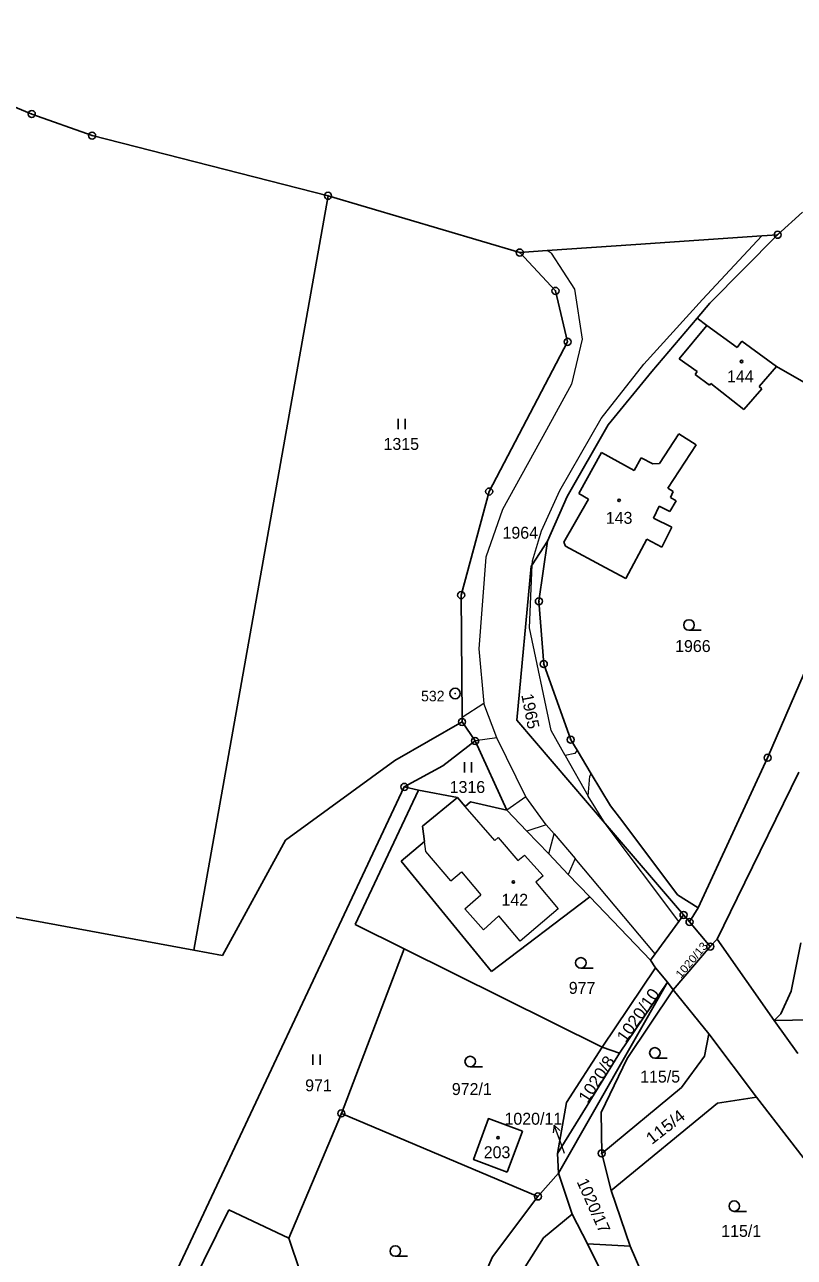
# Model space of a CAD drawing. Extents: x -601131 to -597152, y -1058536 to -1055911.
# Drawn here: x -599499.1 to -599389.4, y -1056477.3 to -1056301.8 of the extents above; entities that cross this region are included whole.
import ezdxf
from ezdxf.enums import TextEntityAlignment as Align

# ---------------------------------------------------------------- set-up
doc = ezdxf.new("R2010")
doc.units = 0
doc.header["$LTSCALE"] = 0.68
for name, color, linetype, lineweight in [('1', 7, 'Continuous', 25), ('3', 7, 'Continuous', 25), ('4', 7, 'Continuous', 13), ('5', 7, 'Continuous', 25), ('7', 7, 'Continuous', 13), ('8', 7, 'Continuous', 25)]:
    doc.layers.add(name, color=color, linetype=linetype, lineweight=lineweight)
doc.layers.add('2', color=7, linetype='Continuous')

msp = doc.modelspace()

# ---------------------------------------------------------------- linework, layer by layer
at = {"layer": '1'}
for p, q in [((-599529.09, -1056301.76), (-599498.05, -1056314.49)), ((-599498.05, -1056314.49), (-599489.45, -1056317.56)), ((-599455.85, -1056326.14), (-599474.95, -1056433.6)), ((-599388.26, -1056328.46), (-599391.8, -1056331.69)), ((-599411.98, -1056333.08), (-599424.64, -1056333.95)), ((-599394.07, -1056331.85), (-599411.98, -1056333.08)), ((-599391.8, -1056331.69), (-599401.45, -1056341.44)), ((-599394.07, -1056331.85), (-599391.8, -1056331.69)), ((-599428.53, -1056334.22), (-599424.64, -1056333.95)), ((-599428.53, -1056334.22), (-599423.44, -1056339.68)), ((-599423.44, -1056339.68), (-599421.72, -1056346.94)), ((-599401.45, -1056341.44), (-599403.27, -1056343.58)), ((-599403.27, -1056343.58), (-599409.73, -1056351.18)), ((-599403.27, -1056343.58), (-599401.88, -1056344.6)), ((-599405.8, -1056349.35), (-599401.88, -1056344.6)), ((-599401.88, -1056344.6), (-599397.54, -1056347.76)), ((-599421.72, -1056346.94), (-599432.89, -1056368.26)), ((-599397.54, -1056347.76), (-599396.88, -1056346.86)), ((-599396.88, -1056346.86), (-599391.94, -1056350.46)), ((-599403.25, -1056351.18), (-599405.8, -1056349.35)), ((-599391.94, -1056350.46), (-599394.41, -1056353.32)), ((-599391.94, -1056350.46), (-599373.7, -1056360.91)), ((-599409.73, -1056351.18), (-599415.96, -1056358.77)), ((-599403.56, -1056351.61), (-599403.25, -1056351.18)), ((-599401.51, -1056353.12), (-599403.56, -1056351.61)), ((-599401.31, -1056352.87), (-599401.51, -1056353.12)), ((-599396.61, -1056356.6), (-599401.31, -1056352.87)), ((-599394.05, -1056353.63), (-599396.61, -1056356.6)), ((-599394.41, -1056353.32), (-599394.05, -1056353.63)), ((-599415.96, -1056358.77), (-599421.77, -1056368.99)), ((-599408.63, -1056364.27), (-599405.85, -1056360.04)), ((-599405.85, -1056360.04), (-599403.42, -1056361.62)), ((-599393.22, -1056406.18), (-599373.7, -1056360.91)), ((-599420.12, -1056368.56), (-599416.89, -1056362.69)), ((-599416.89, -1056362.69), (-599412.24, -1056365.26)), ((-599403.42, -1056361.62), (-599407.44, -1056367.8)), ((-599412.24, -1056365.26), (-599411.23, -1056363.44)), ((-599411.23, -1056363.44), (-599409.58, -1056364.34)), ((-599409.58, -1056364.34), (-599408.63, -1056364.27)), ((-599432.89, -1056368.26), (-599436.88, -1056383.02)), ((-599407.44, -1056367.8), (-599406.69, -1056368.28)), ((-599406.69, -1056368.28), (-599407.08, -1056369.09)), ((-599421.77, -1056368.99), (-599424.57, -1056375.34)), ((-599422.25, -1056375.49), (-599418.74, -1056369.35)), ((-599418.74, -1056369.35), (-599420.12, -1056368.56)), ((-599406.27, -1056369.57), (-599407.15, -1056371.12)), ((-599407.08, -1056369.09), (-599406.27, -1056369.57)), ((-599408.65, -1056370.37), (-599409.49, -1056372.05)), ((-599407.15, -1056371.12), (-599408.65, -1056370.37)), ((-599409.49, -1056372.05), (-599406.86, -1056373.35)), ((-599406.86, -1056373.35), (-599408.27, -1056376.19)), ((-599424.57, -1056375.34), (-599426.76, -1056378.69)), ((-599424.57, -1056375.34), (-599425.81, -1056383.89)), ((-599422.03, -1056376.04), (-599422.25, -1056375.49)), ((-599410.45, -1056375.05), (-599413.41, -1056380.67)), ((-599408.27, -1056376.19), (-599410.45, -1056375.05)), ((-599416.35, -1056379.09), (-599422.03, -1056376.04)), ((-599426.9, -1056378.9), (-599428.95, -1056400.81)), ((-599426.76, -1056378.69), (-599426.9, -1056378.9)), ((-599413.41, -1056380.67), (-599416.35, -1056379.09)), ((-599436.88, -1056383.02), (-599436.76, -1056400.43)), ((-599425.81, -1056383.89), (-599425.11, -1056392.84)), ((-599425.11, -1056392.84), (-599421.27, -1056403.61)), ((-599436.76, -1056401.08), (-599446.33, -1056406.57)), ((-599436.76, -1056400.43), (-599436.76, -1056401.08)), ((-599436.76, -1056401.08), (-599434.89, -1056403.79)), ((-599428.95, -1056400.81), (-599416.35, -1056415.54)), ((-599420.36, -1056405.12), (-599421.27, -1056403.61)), ((-599439.48, -1056407.32), (-599434.89, -1056403.79)), ((-599434.89, -1056403.79), (-599430.37, -1056413.65)), ((-599420.36, -1056405.12), (-599418.36, -1056408.45)), ((-599446.33, -1056406.57), (-599461.89, -1056417.94)), ((-599403.1, -1056427.58), (-599393.22, -1056406.18)), ((-599444.98, -1056410.33), (-599439.48, -1056407.32)), ((-599418.36, -1056408.45), (-599415.59, -1056413.04)), ((-599388.77, -1056408.24), (-599397.57, -1056426.19)), ((-599444.98, -1056410.33), (-599484.45, -1056494.21)), ((-599444.98, -1056410.33), (-599442.97, -1056410.79)), ((-599451.98, -1056429.95), (-599442.97, -1056410.79)), ((-599442.97, -1056410.79), (-599437.4, -1056411.83)), ((-599442.37, -1056415.95), (-599437.4, -1056411.83)), ((-599437.4, -1056411.83), (-599436.29, -1056413.11)), ((-599474.95, -1056433.6), (-599583.89, -1056413.57)), ((-599435.55, -1056412.47), (-599436.29, -1056413.11)), ((-599435.55, -1056412.47), (-599430.37, -1056413.65)), ((-599430.37, -1056413.65), (-599427.52, -1056416.63)), ((-599415.59, -1056413.04), (-599413.85, -1056415.3)), ((-599416.35, -1056415.54), (-599405.2, -1056428.57)), ((-599413.85, -1056415.3), (-599406.08, -1056425.73)), ((-599442.1, -1056418.09), (-599442.37, -1056415.95)), ((-599424.4, -1056419.89), (-599427.52, -1056416.63)), ((-599461.89, -1056417.94), (-599470.88, -1056434.35)), ((-599442.1, -1056418.09), (-599445.41, -1056420.93)), ((-599445.41, -1056420.93), (-599432.54, -1056436.64)), ((-599421.62, -1056422.79), (-599424.4, -1056419.89)), ((-599421.62, -1056422.79), (-599418.55, -1056425.99)), ((-599418.55, -1056425.99), (-599432.54, -1056436.64)), ((-599418.55, -1056425.99), (-599409.9, -1056435.03)), ((-599406.08, -1056425.73), (-599403.1, -1056427.58)), ((-599397.57, -1056426.19), (-599400.42, -1056432.01)), ((-599404.35, -1056429.57), (-599403.1, -1056427.58)), ((-599444.99, -1056433.39), (-599451.98, -1056429.95)), ((-599405.88, -1056429.51), (-599409.22, -1056434.1)), ((-599405.2, -1056428.57), (-599405.88, -1056429.51)), ((-599404.35, -1056429.57), (-599405.2, -1056428.57)), ((-599401.4, -1056433.08), (-599404.35, -1056429.57)), ((-599453.95, -1056456.84), (-599444.99, -1056433.39)), ((-599444.99, -1056433.39), (-599416.78, -1056447.42)), ((-599406.68, -1056439.22), (-599401.4, -1056433.08)), ((-599400.42, -1056432.01), (-599401.4, -1056433.08)), ((-599400.42, -1056432.01), (-599392.27, -1056443.62)), ((-599388.49, -1056432.53), (-599389.89, -1056439.45)), ((-599470.88, -1056434.35), (-599474.95, -1056433.6)), ((-599409.9, -1056435.03), (-599409.22, -1056434.1)), ((-599409.9, -1056435.03), (-599409.18, -1056436.11)), ((-599409.18, -1056436.11), (-599416.78, -1056447.42)), ((-599409.18, -1056436.11), (-599407.49, -1056438.17)), ((-599422.99, -1056465.36), (-599407.49, -1056438.17)), ((-599407.49, -1056438.17), (-599414.32, -1056448.25)), ((-599407.49, -1056438.17), (-599406.68, -1056439.22)), ((-599406.68, -1056439.22), (-599413.25, -1056449)), ((-599401.61, -1056445.52), (-599406.68, -1056439.22)), ((-599389.89, -1056439.45), (-599391.33, -1056442.64)), ((-599391.33, -1056442.64), (-599392.27, -1056443.62)), ((-599392.27, -1056443.62), (-599387.07, -1056443.53)), ((-599392.27, -1056443.62), (-599388.94, -1056448.31)), ((-599402.22, -1056448.71), (-599401.61, -1056445.52)), ((-599394.79, -1056454.54), (-599401.61, -1056445.52)), ((-599416.78, -1056447.42), (-599421.88, -1056455.31)), ((-599416.78, -1056447.42), (-599414.32, -1056448.25)), ((-599414.32, -1056448.25), (-599423.15, -1056462.53)), ((-599413.25, -1056449), (-599416.92, -1056456.69)), ((-599405.49, -1056453.16), (-599402.22, -1056448.71)), ((-599416.86, -1056462.53), (-599405.49, -1056453.16)), ((-599400.38, -1056455.37), (-599394.79, -1056454.54)), ((-599394.79, -1056454.54), (-599377.16, -1056477.43)), ((-599421.88, -1056455.31), (-599423.15, -1056462.53)), ((-599415.52, -1056467.82), (-599400.38, -1056455.37)), ((-599425.94, -1056468.67), (-599453.95, -1056456.84)), ((-599416.92, -1056456.69), (-599416.86, -1056462.53)), ((-599428.16, -1056459.39), (-599430.33, -1056465.23)), ((-599423.15, -1056462.53), (-599422.99, -1056465.36)), ((-599416.86, -1056462.53), (-599415.52, -1056467.82)), ((-599422.99, -1056465.36), (-599425.94, -1056468.67)), ((-599421.06, -1056471.2), (-599422.99, -1056465.36)), ((-599412.79, -1056475.76), (-599415.52, -1056467.82)), ((-599425.94, -1056468.67), (-599432.42, -1056477.26)), ((-599469.97, -1056470.57), (-599482.19, -1056495.19)), ((-599469.97, -1056470.57), (-599461.42, -1056474.62)), ((-599421.06, -1056471.2), (-599425.14, -1056474.58)), ((-599418.88, -1056475.43), (-599421.06, -1056471.2)), ((-599425.14, -1056474.58), (-599428.89, -1056480.48)), ((-599418.88, -1056475.43), (-599412.79, -1056475.76)), ((-599413.77, -1056485.74), (-599418.88, -1056475.43)), ((-599432.42, -1056477.26), (-599435.66, -1056484.55)), ((-599408.6, -1056485.47), (-599412.79, -1056475.76))]:
    msp.add_line(p, q, dxfattribs=at)
for points in [[(-599489.45, -1056317.56), (-599455.85, -1056326.14), (-599428.53, -1056334.22)], [(-599451.49, -1056504.11), (-599461.42, -1056474.62), (-599453.95, -1056456.84)], [(-599428.16, -1056459.39), (-599433, -1056457.59), (-599435.12, -1056463.41), (-599430.33, -1056465.23)]]:
    msp.add_lwpolyline(points, dxfattribs=at)
at = {"layer": '3'}
for p, q in [((-599445.841, -1056359.39), (-599445.841, -1056357.89)), ((-599444.84, -1056359.39), (-599444.84, -1056357.89)), ((-599404.423, -1056388.03), (-599402.673, -1056388.03)), ((-599436.411, -1056408.29), (-599436.411, -1056406.79)), ((-599435.41, -1056408.29), (-599435.41, -1056406.79)), ((-599419.833, -1056436.15), (-599418.083, -1056436.15)), ((-599457.991, -1056449.94), (-599457.991, -1056448.44)), ((-599456.99, -1056449.94), (-599456.99, -1056448.44)), ((-599409.283, -1056448.97), (-599407.533, -1056448.97)), ((-599435.593, -1056450.21), (-599433.843, -1056450.21)), ((-599397.973, -1056470.8), (-599396.223, -1056470.8)), ((-599446.253, -1056477.2), (-599444.503, -1056477.2))]:
    msp.add_line(p, q, dxfattribs=at)
for centre in [(-599404.4229, -1056387.2798), (-599419.8329, -1056435.3998), (-599409.2829, -1056448.2198), (-599435.5929, -1056449.4598), (-599397.9729, -1056470.0498), (-599446.2529, -1056476.4498)]:
    msp.add_circle(centre, 0.75, dxfattribs=at)
at = {"layer": '4'}
for p, q in [((-599402.52, -1056340.9), (-599394.07, -1056331.85)), ((-599424.08, -1056334.31), (-599424.64, -1056333.95)), ((-599424.08, -1056334.31), (-599420.73, -1056339.44)), ((-599420.73, -1056339.44), (-599419.64, -1056346.58)), ((-599410.88, -1056350.12), (-599402.52, -1056340.9)), ((-599419.64, -1056346.58), (-599421.16, -1056352.96)), ((-599416.95, -1056357.87), (-599410.88, -1056350.12)), ((-599421.16, -1056352.96), (-599424.7, -1056359.48)), ((-599422.84, -1056368.12), (-599416.95, -1056357.87)), ((-599424.7, -1056359.48), (-599431.01, -1056370.83)), ((-599425.44, -1056373.88), (-599422.84, -1056368.12)), ((-599431.01, -1056370.83), (-599433.35, -1056377.62)), ((-599426.74, -1056378.15), (-599425.44, -1056373.88)), ((-599433.35, -1056377.62), (-599434.38, -1056390.65)), ((-599427.14, -1056387.68), (-599426.76, -1056378.69)), ((-599426.76, -1056378.69), (-599426.74, -1056378.15)), ((-599424.05, -1056402.32), (-599427.14, -1056387.68)), ((-599434.38, -1056390.65), (-599433.64, -1056398.44)), ((-599433.64, -1056398.44), (-599436.76, -1056400.43)), ((-599431.81, -1056403.34), (-599433.64, -1056398.44)), ((-599431.81, -1056403.34), (-599434.89, -1056403.79)), ((-599427.69, -1056411.77), (-599431.81, -1056403.34)), ((-599422.06, -1056405.88), (-599424.05, -1056402.32)), ((-599420.36, -1056405.12), (-599420.67, -1056405.57)), ((-599420.67, -1056405.57), (-599422.06, -1056405.88)), ((-599422.06, -1056405.88), (-599418.81, -1056411.64)), ((-599418.81, -1056411.64), (-599418.53, -1056408.79)), ((-599418.53, -1056408.79), (-599418.36, -1056408.45)), ((-599416.35, -1056415.54), (-599418.81, -1056411.64)), ((-599432.08, -1056417.95), (-599436.29, -1056413.11)), ((-599424.76, -1056415.73), (-599427.52, -1056416.63)), ((-599423.63, -1056417), (-599424.76, -1056415.73)), ((-599405.88, -1056429.51), (-599416.35, -1056415.54)), ((-599432.08, -1056417.95), (-599431.6, -1056417.54)), ((-599431.6, -1056417.54), (-599428.82, -1056420.84)), ((-599424.4, -1056419.89), (-599423.63, -1056417)), ((-599423.63, -1056417), (-599420.66, -1056420.51)), ((-599441.91, -1056419.54), (-599442.1, -1056418.09)), ((-599438.34, -1056423.7), (-599441.91, -1056419.54)), ((-599428.82, -1056420.84), (-599427.88, -1056420.04)), ((-599425.21, -1056423), (-599427.88, -1056420.04)), ((-599420.66, -1056420.51), (-599421.62, -1056422.79)), ((-599409.22, -1056434.1), (-599420.66, -1056420.51)), ((-599438.34, -1056423.7), (-599436.81, -1056422.42)), ((-599436.81, -1056422.42), (-599434.06, -1056425.71)), ((-599425.21, -1056423), (-599426.25, -1056423.9)), ((-599426.25, -1056423.9), (-599423.05, -1056427.69)), ((-599436.35, -1056427.7), (-599434.06, -1056425.71)), ((-599433.72, -1056430.71), (-599436.35, -1056427.7)), ((-599423.05, -1056427.69), (-599428.46, -1056432.3)), ((-599431.52, -1056428.69), (-599433.72, -1056430.71)), ((-599428.46, -1056432.3), (-599431.52, -1056428.69))]:
    msp.add_line(p, q, dxfattribs=at)
msp.add_lwpolyline([(-599424.76, -1056415.73), (-599427.69, -1056411.77), (-599430.37, -1056413.65)], dxfattribs=at)
at = {"layer": '5'}
for centre in [(-599396.9368, -1056349.7392), (-599414.3768, -1056369.5292), (-599429.4468, -1056423.8792), (-599431.6268, -1056460.3092)]:
    msp.add_circle(centre, 0.175, dxfattribs=at)
at = {"layer": '7'}
msp.add_line((-599423.636, -1056458.51), (-599423.764, -1056459.622), dxfattribs=at)
msp.add_lwpolyline([(-599422.18, -1056462.55), (-599422.61, -1056461.33), (-599423.636, -1056458.51), (-599422.823, -1056459.28)], dxfattribs=at)
at = {"layer": '8'}
for centre, radius in [((-599498.05, -1056314.4899), 0.5), ((-599498.05, -1056314.4899), 0.0303), ((-599489.45, -1056317.5599), 0.5), ((-599489.45, -1056317.5599), 0.0303), ((-599455.85, -1056326.1399), 0.5), ((-599455.85, -1056326.1399), 0.0303), ((-599391.8, -1056331.6899), 0.5), ((-599391.8, -1056331.6899), 0.0303), ((-599428.53, -1056334.2199), 0.5), ((-599428.53, -1056334.2199), 0.0303), ((-599423.44, -1056339.6799), 0.5), ((-599423.44, -1056339.6799), 0.0303), ((-599421.72, -1056346.9399), 0.5), ((-599421.72, -1056346.9399), 0.0303), ((-599432.89, -1056368.2599), 0.5), ((-599432.89, -1056368.2599), 0.0303), ((-599436.88, -1056383.0199), 0.5), ((-599436.88, -1056383.0199), 0.0303), ((-599425.81, -1056383.8899), 0.5), ((-599425.81, -1056383.8899), 0.0303), ((-599425.11, -1056392.8399), 0.5), ((-599425.11, -1056392.8399), 0.0303), ((-599437.75, -1056397.0298), 0.75), ((-599437.75, -1056397.0298), 0.03), ((-599436.76, -1056401.0799), 0.5), ((-599436.76, -1056401.0799), 0.0303), ((-599434.89, -1056403.7899), 0.5), ((-599421.27, -1056403.6099), 0.5), ((-599421.27, -1056403.6099), 0.0303), ((-599434.89, -1056403.7899), 0.0303), ((-599393.22, -1056406.1799), 0.5), ((-599393.22, -1056406.1799), 0.0303), ((-599444.98, -1056410.3299), 0.5), ((-599444.98, -1056410.3299), 0.0303), ((-599405.2, -1056428.5699), 0.5), ((-599405.2, -1056428.5699), 0.0303), ((-599404.35, -1056429.5699), 0.5), ((-599404.35, -1056429.5699), 0.0303), ((-599401.4, -1056433.0799), 0.5), ((-599401.4, -1056433.0799), 0.0303), ((-599453.95, -1056456.8399), 0.5), ((-599453.95, -1056456.8399), 0.0303), ((-599416.86, -1056462.5299), 0.5), ((-599416.86, -1056462.5299), 0.0303), ((-599425.94, -1056468.6699), 0.5), ((-599425.94, -1056468.6699), 0.0303)]:
    msp.add_circle(centre, radius, dxfattribs=at)

# ---------------------------------------------------------------- texts
at = {"layer": '2'}
for s, p in [('144', (-599397.109, -1056352.712)), ('1315', (-599445.41, -1056362.332)), ('143', (-599414.379, -1056372.862)), ('1964', (-599428.46, -1056374.982)), ('1966', (-599403.87, -1056391.122)), ('1316', (-599435.99, -1056411.202)), ('1020/11', (-599426.599, -1056458.455)), ('203', (-599431.769, -1056463.225))]:
    msp.add_text(s, height=1.7, dxfattribs=at).set_placement(p, align=Align.CENTER)
msp.add_text('1965', height=1.7, rotation=281, dxfattribs=at).set_placement((-599427.8428, -1056399.7068), align=Align.CENTER)
for s, p in [('142', (-599431.14, -1056427.265)), ('977', (-599421.55, -1056439.814)), ('115/5', (-599411.38, -1056452.445)), ('971', (-599459.1, -1056453.695)), ('972/1', (-599438.21, -1056454.225)), ('115/1', (-599399.83, -1056474.425))]:
    msp.add_text(s, height=1.7, dxfattribs=at).set_placement(p)
for s, height, rotation, width, p in [('1020/13', 1.14, 50, 1.1, (-599405.571, -1056437.683)), ('1020/10', 1.7, 55, 1.05, (-599413.461, -1056446.873)), ('1020/8', 1.7, 57, 1.05, (-599418.873, -1056455.481)), ('115/4', 1.7, 38, 1.1, (-599409.728, -1056461.364))]:
    msp.add_text(s, height=height, rotation=rotation, dxfattribs=dict(at, width=width)).set_placement(p)
msp.add_text('1020/17', height=1.7, rotation=294, dxfattribs=at).set_placement((-599420.458, -1056466.562))
at = {"layer": '8'}
msp.add_text('532', height=1.5, dxfattribs=at).set_placement((-599439.249, -1056398.147), align=Align.RIGHT)

doc.saveas('drawing.dxf')
